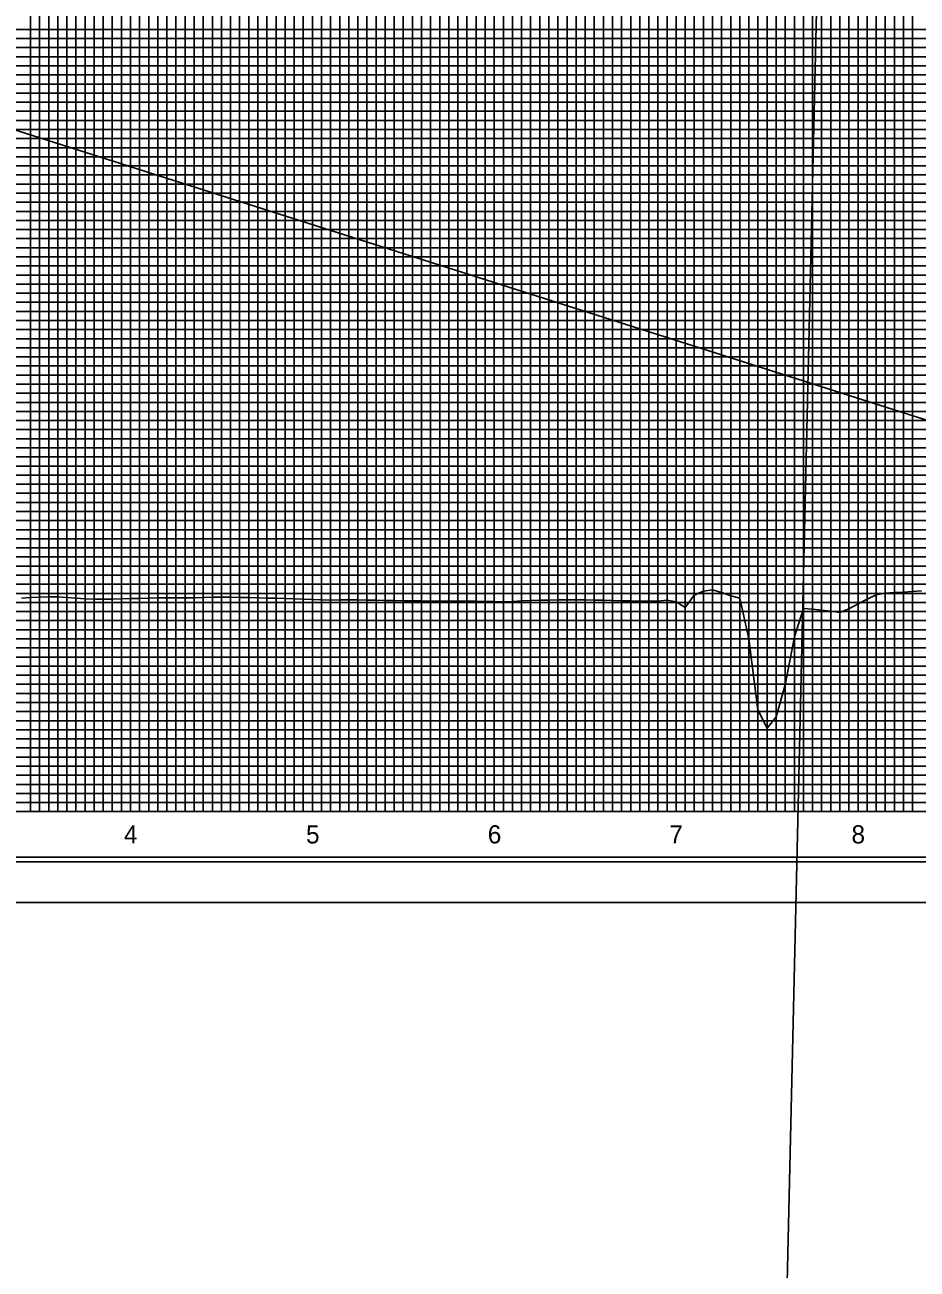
# Model space of a CAD drawing. Extents: x 2345490 to 2436403, y 465165 to 573888.
# Drawn here: x 2411237 to 2411728, y 518231 to 518915 of the extents above; entities that cross this region are included whole.
import ezdxf

# ---------------------------------------------------------------- set-up
doc = ezdxf.new("R2010")
doc.units = 0
for name, color, linetype in [('Old_Level_1', 7, 'Continuous'), ('Old_Level_18', 7, 'Continuous'), ('Old_Level_2', 7, 'Continuous'), ('Old_Level_41', 7, 'Continuous'), ('Old_Level_42', 7, 'Continuous'), ('Old_Level_43', 7, 'Continuous'), ('Old_Level_50', 7, 'Continuous'), ('Old_Level_51', 7, 'Continuous'), ('Old_Level_63', 7, 'Continuous')]:
    doc.layers.add(name, color=color, linetype=linetype)

msp = doc.modelspace()

# ---------------------------------------------------------------- linework, layer by layer
at = {"layer": 'Old_Level_1'}
for points in [[(2411395.325, 518598.98475), (2411400.325, 518598.82875), (2411405.325, 518598.682), (2411410.325, 518598.75025), (2411415.325, 518598.8525), (2411420.325, 518598.783), (2411425.325, 518598.686), (2411430.325, 518598.59425), (2411435.325, 518598.5075), (2411440.325, 518598.426), (2411445.325, 518598.34975), (2411450.325, 518598.27875), (2411455.325, 518598.21275), (2411460.325, 518598.1655), (2411465.325, 518598.126), (2411470.325, 518598.092), (2411475.325, 518598.063), (2411480.325, 518598.0395), (2411485.325, 518598.02125), (2411490.325, 518597.99725), (2411495.325, 518597.9345), (2411500.325, 518597.8095), (2411505.325, 518597.96425), (2411510.325, 518598.19725), (2411515.325, 518598.44175), (2411520.325, 518598.59925), (2411525.325, 518598.69225), (2411530.325, 518598.7865), (2411535.325, 518598.882), (2411540.325, 518598.91475), (2411545.325, 518598.7975), (2411550.325, 518598.6835), (2411555.325, 518598.5725), (2411560.325, 518598.465), (2411565.325, 518598.3605), (2411570.325, 518598.25975), (2411575.325, 518598.162), (2411580.325, 518598.1435), (2411585.325, 518598.13625), (2411590.325, 518598.67625), (2411595.325, 518597.67275), (2411600.325, 518594.612), (2411605.325, 518601.43525), (2411610.325, 518603.541), (2411615.325, 518604.4015), (2411620.325, 518602.7835), (2411625.325, 518601.10625), (2411630.325, 518599.7775), (2411635.325, 518577.3245), (2411640.325, 518538.38375), (2411645.325, 518528.2755), (2411650.325, 518534.60325), (2411655.325, 518552.0595), (2411660.325, 518578.53775), (2411665.325, 518594.14075), (2411670.325, 518593.6225), (2411675.325, 518593.13325), (2411680.325, 518592.5785), (2411685.325, 518591.92875), (2411690.325, 518593.857), (2411695.325, 518596.55175), (2411700.325, 518599.15175), (2411705.325, 518601.5265), (2411710.325, 518602.44875), (2411715.325, 518602.7755), (2411720.325, 518603.11075), (2411725.325, 518603.45425), (2411730.325, 518603.80575)], [(2411235.325, 518599.83525), (2411240.325, 518600.069), (2411245.325, 518600.30975), (2411250.325, 518600.55725), (2411255.325, 518600.51975), (2411260.325, 518600.13075), (2411265.325, 518599.74925), (2411270.325, 518599.37525), (2411275.325, 518599.10925), (2411280.325, 518599.153), (2411285.325, 518599.219), (2411290.325, 518599.344), (2411295.325, 518599.4935), (2411300.325, 518599.64125), (2411305.325, 518599.787), (2411310.325, 518599.9305), (2411315.325, 518599.93425), (2411320.325, 518599.932), (2411325.325, 518599.92825), (2411330.325, 518599.92325), (2411335.325, 518600.0605), (2411340.325, 518600.36475), (2411345.325, 518600.29), (2411350.325, 518600.21125), (2411355.325, 518600.13725), (2411360.325, 518600.06375), (2411365.325, 518599.90975), (2411370.325, 518599.766), (2411375.325, 518599.69275), (2411380.325, 518599.50575), (2411385.325, 518599.32325), (2411390.325, 518599.1495), (2411395.325, 518598.98475)]]:
    msp.add_lwpolyline(points, dxfattribs=at)
at = {"layer": 'Old_Level_18'}
msp.add_lwpolyline([(2412345.325, 519507.40475), (2410845.325, 519507.40475), (2410845.325, 518457.40475), (2412345.325, 518457.40475)], close=True, dxfattribs=at)
at = {"layer": 'Old_Level_2'}
for p, q in [((2411722.59175, 521117.51825), (2411239.1575, 499960.77)), ((2411225.325, 518859.28375), (2411745.325, 518693.59875))]:
    msp.add_line(p, q, dxfattribs=at)
at = {"layer": 'Old_Level_41'}
msp.add_line((2412345.325, 518482.40475), (2410845.325, 518482.40475), dxfattribs=at)
for points in [[(2411195.325, 518482.40475), (2411245.325, 518482.40475), (2411245.325, 519507.40475)], [(2411270.325, 519507.40475), (2411270.325, 518482.40475), (2411320.325, 518482.40475), (2411320.325, 519507.40475)], [(2411295.325, 519507.40475), (2411295.325, 518482.40475), (2411345.325, 518482.40475), (2411345.325, 519507.40475)], [(2411370.325, 519507.40475), (2411370.325, 518482.40475), (2411420.325, 518482.40475), (2411420.325, 519507.40475)], [(2411395.325, 519507.40475), (2411395.325, 518482.40475), (2411445.325, 518482.40475), (2411445.325, 519507.40475)], [(2411470.325, 519507.40475), (2411470.325, 518482.40475), (2411520.325, 518482.40475), (2411520.325, 519507.40475)], [(2411495.325, 519507.40475), (2411495.325, 518482.40475), (2411545.325, 518482.40475), (2411545.325, 519507.40475)], [(2411570.325, 519507.40475), (2411570.325, 518482.40475), (2411620.325, 518482.40475), (2411620.325, 519507.40475)], [(2411595.325, 519507.40475), (2411595.325, 518482.40475), (2411645.325, 518482.40475), (2411645.325, 519507.40475)], [(2411670.325, 519507.40475), (2411670.325, 518482.40475), (2411720.325, 518482.40475), (2411720.325, 519507.40475)], [(2411695.325, 519507.40475), (2411695.325, 518482.40475), (2411745.325, 518482.40475), (2411745.325, 519507.40475)], [(2412345.325, 518907.40475), (2410845.325, 518907.40475), (2410845.325, 518857.40475), (2412345.325, 518857.40475)], [(2412345.325, 518832.40475), (2410845.325, 518832.40475), (2410845.325, 518882.40475), (2412345.325, 518882.40475)], [(2412345.325, 518807.40475), (2410845.325, 518807.40475), (2410845.325, 518757.40475), (2412345.325, 518757.40475)], [(2412345.325, 518732.40475), (2410845.325, 518732.40475), (2410845.325, 518782.40475), (2412345.325, 518782.40475)], [(2412345.325, 518707.40475), (2410845.325, 518707.40475), (2410845.325, 518657.40475), (2412345.325, 518657.40475)], [(2412345.325, 518607.40475), (2410845.325, 518607.40475), (2410845.325, 518557.40475), (2412345.325, 518557.40475)], [(2412345.325, 518532.40475), (2410845.325, 518532.40475), (2410845.325, 518582.40475), (2412345.325, 518582.40475)], [(2412345.325, 518507.40475), (2410845.325, 518507.40475)]]:
    msp.add_lwpolyline(points, dxfattribs=at)
at = {"layer": 'Old_Level_42'}
msp.add_lwpolyline([(2412345.325, 518632.40475), (2410845.325, 518632.40475), (2410845.325, 518682.40475), (2412345.325, 518682.40475)], dxfattribs=at)
at = {"layer": 'Old_Level_43'}
for points in [[(2411225.325, 518482.40475), (2411240.325, 518482.40475), (2411240.325, 519507.40475)], [(2411250.325, 519507.40475), (2411250.325, 518482.40475), (2411255.325, 518482.40475), (2411255.325, 519507.40475)], [(2411260.325, 519507.40475), (2411260.325, 518482.40475), (2411265.325, 518482.40475), (2411265.325, 519507.40475)], [(2411275.325, 519507.40475), (2411275.325, 518482.40475), (2411280.325, 518482.40475), (2411280.325, 519507.40475)], [(2411285.325, 519507.40475), (2411285.325, 518482.40475), (2411290.325, 518482.40475), (2411290.325, 519507.40475)], [(2411300.325, 519507.40475), (2411300.325, 518482.40475), (2411305.325, 518482.40475), (2411305.325, 519507.40475)], [(2411310.325, 519507.40475), (2411310.325, 518482.40475), (2411315.325, 518482.40475), (2411315.325, 519507.40475)], [(2411325.325, 519507.40475), (2411325.325, 518482.40475), (2411330.325, 518482.40475), (2411330.325, 519507.40475)], [(2411335.325, 519507.40475), (2411335.325, 518482.40475), (2411340.325, 518482.40475), (2411340.325, 519507.40475)], [(2411350.325, 519507.40475), (2411350.325, 518482.40475), (2411355.325, 518482.40475), (2411355.325, 519507.40475)], [(2411360.325, 519507.40475), (2411360.325, 518482.40475), (2411365.325, 518482.40475), (2411365.325, 519507.40475)], [(2411375.325, 519507.40475), (2411375.325, 518482.40475)], [(2411380.325, 519507.40475), (2411380.325, 518482.40475), (2411385.325, 518482.40475), (2411385.325, 519507.40475), (2411390.325, 519507.40475), (2411390.325, 518482.40475), (2411400.325, 518482.40475), (2411400.325, 519507.40475), (2411405.325, 519507.40475), (2411405.325, 518482.40475), (2411410.325, 518482.40475), (2411410.325, 519507.40475), (2411415.325, 519507.40475), (2411415.325, 518482.40475)], [(2411425.325, 518482.40475), (2411425.325, 519507.40475)], [(2411430.325, 519507.40475), (2411430.325, 518482.40475), (2411435.325, 518482.40475), (2411435.325, 519507.40475)], [(2411440.325, 519507.40475), (2411440.325, 518482.40475), (2411450.325, 518482.40475), (2411450.325, 519507.40475)], [(2411455.325, 519507.40475), (2411455.325, 518482.40475), (2411455.325, 518482.40475), (2411460.325, 518482.40475), (2411460.325, 519507.40475)], [(2411465.325, 519507.40475), (2411465.325, 518482.40475), (2411475.325, 518482.40475), (2411475.325, 519507.40475)], [(2411480.325, 519507.40475), (2411480.325, 518482.40475), (2411485.325, 518482.40475), (2411485.325, 519507.40475)], [(2411490.325, 519507.40475), (2411490.325, 518482.40475), (2411500.325, 518482.40475), (2411500.325, 519507.40475)], [(2411505.325, 519507.40475), (2411505.325, 518482.40475), (2411510.325, 518482.40475), (2411510.325, 519507.40475)], [(2411515.325, 519507.40475), (2411515.325, 518482.40475), (2411525.325, 518482.40475), (2411525.325, 519507.40475)], [(2411530.325, 519507.40475), (2411530.325, 518482.40475), (2411535.325, 518482.40475), (2411535.325, 519507.40475)], [(2411540.325, 519507.40475), (2411540.325, 518482.40475), (2411550.325, 518482.40475), (2411550.325, 519507.40475)], [(2411555.325, 519507.40475), (2411555.325, 518482.40475), (2411560.325, 518482.40475), (2411560.325, 519507.40475)], [(2411565.325, 519507.40475), (2411565.325, 518482.40475), (2411575.325, 518482.40475), (2411575.325, 519507.40475)], [(2411580.325, 519507.40475), (2411580.325, 518482.40475), (2411585.325, 518482.40475), (2411585.325, 519507.40475)], [(2411590.325, 519507.40475), (2411590.325, 518482.40475), (2411600.325, 518482.40475), (2411600.325, 519507.40475)], [(2411605.325, 519507.40475), (2411605.325, 518482.40475)], [(2411605.325, 518482.40475), (2411610.325, 518482.40475), (2411610.325, 519506.80475)], [(2411615.325, 519506.80475), (2411615.325, 518482.40475), (2411625.325, 518482.40475), (2411625.325, 519507.40475)], [(2411630.325, 519507.40475), (2411630.325, 518482.40475), (2411635.325, 518482.40475), (2411635.325, 519507.40475)], [(2411640.325, 519507.40475), (2411640.325, 518482.40475), (2411650.325, 518482.40475), (2411650.325, 519507.40475)], [(2411655.325, 519507.40475), (2411655.325, 518482.40475), (2411660.325, 518482.40475), (2411660.325, 519507.40475)], [(2411665.325, 519507.40475), (2411665.325, 518482.40475), (2411675.325, 518482.40475), (2411675.325, 519507.40475)], [(2411680.325, 519507.40475), (2411680.325, 518482.40475), (2411685.325, 518482.40475), (2411685.325, 519507.40475)], [(2411690.325, 519507.40475), (2411690.325, 518482.40475), (2411700.325, 518482.40475), (2411700.325, 519507.40475)], [(2411705.325, 519507.40475), (2411705.325, 518482.40475), (2411710.325, 518482.40475), (2411710.325, 519507.40475)], [(2411715.325, 519507.40475), (2411715.325, 518482.40475), (2411725.325, 518482.40475), (2411725.325, 519507.40475)], [(2412295.325, 518912.40475), (2410895.325, 518912.40475), (2410895.325, 518902.40475), (2412295.325, 518902.40475)], [(2412295.325, 518897.40475), (2410895.325, 518897.40475), (2410895.325, 518892.40475), (2412295.325, 518892.40475)], [(2412295.325, 518887.40475), (2410895.325, 518887.40475), (2410895.325, 518877.40475), (2412295.325, 518877.40475)], [(2412295.325, 518872.40475), (2410895.325, 518872.40475), (2410895.325, 518867.40475), (2412295.325, 518867.40475)], [(2412295.325, 518862.40475), (2410895.325, 518862.40475), (2410895.325, 518852.40475), (2412295.325, 518852.40475)], [(2412295.325, 518847.40475), (2410895.325, 518847.40475), (2410895.325, 518842.40475), (2412295.325, 518842.40475)], [(2412295.325, 518837.40475), (2410895.325, 518837.40475), (2410895.325, 518827.40475), (2412295.325, 518827.40475)], [(2412295.325, 518822.40475), (2410895.325, 518822.40475), (2410895.325, 518817.40475), (2412295.325, 518817.40475)], [(2412295.325, 518812.40475), (2410895.325, 518812.40475), (2410895.325, 518802.40475), (2412295.325, 518802.40475)], [(2412295.325, 518797.40475), (2410895.325, 518797.40475), (2410895.325, 518792.40475), (2412295.325, 518792.40475)], [(2412295.325, 518787.40475), (2410895.325, 518787.40475), (2410895.325, 518777.40475), (2412295.325, 518777.40475)], [(2412295.325, 518772.40475), (2410895.325, 518772.40475), (2410895.325, 518767.40475), (2412295.325, 518767.40475)], [(2412295.325, 518762.40475), (2410895.325, 518762.40475), (2410895.325, 518752.40475), (2412295.325, 518752.40475)], [(2412295.325, 518747.40475), (2410895.325, 518747.40475), (2410895.325, 518742.40475), (2412295.325, 518742.40475)], [(2412295.325, 518737.40475), (2410895.325, 518737.40475), (2410895.325, 518727.40475), (2412295.325, 518727.40475)], [(2412295.325, 518722.40475), (2410895.325, 518722.40475), (2410895.325, 518717.40475), (2412295.325, 518717.40475)], [(2412295.325, 518712.40475), (2410895.325, 518712.40475), (2410895.325, 518702.40475), (2412295.325, 518702.40475)], [(2412295.325, 518697.40475), (2410895.325, 518697.40475), (2410895.325, 518692.40475), (2412295.325, 518692.40475)], [(2412295.325, 518687.40475), (2410895.325, 518687.40475)], [(2410895.325, 518677.40475), (2412295.325, 518677.40475)], [(2412295.325, 518672.40475), (2410895.325, 518672.40475), (2410895.325, 518667.40475), (2412295.325, 518667.40475)], [(2412295.325, 518662.40475), (2410895.325, 518662.40475)], [(2410895.325, 518652.40475), (2412295.325, 518652.40475)], [(2412295.325, 518647.40475), (2410895.325, 518647.40475), (2410895.325, 518642.40475), (2412295.325, 518642.40475)], [(2412295.325, 518637.40475), (2410895.325, 518637.40475), (2410895.325, 518627.40475), (2412295.325, 518627.40475)], [(2412295.325, 518622.40475), (2410895.325, 518622.40475), (2410895.325, 518617.40475), (2412295.325, 518617.40475)], [(2412295.325, 518612.40475), (2410895.325, 518612.40475), (2410895.325, 518602.40475), (2412295.325, 518602.40475)], [(2412295.325, 518597.40475), (2410895.325, 518597.40475), (2410895.325, 518592.40475), (2412295.325, 518592.40475)], [(2412295.325, 518587.40475), (2410895.325, 518587.40475), (2410895.325, 518577.40475), (2412295.325, 518577.40475)], [(2412295.325, 518572.40475), (2410895.325, 518572.40475), (2410895.325, 518567.40475), (2412295.325, 518567.40475)], [(2412295.325, 518562.40475), (2410895.325, 518562.40475), (2410895.325, 518552.40475), (2412295.325, 518552.40475)], [(2412295.325, 518547.40475), (2410895.325, 518547.40475), (2410895.325, 518542.40475), (2412295.325, 518542.40475)], [(2412295.325, 518537.40475), (2410895.325, 518537.40475), (2410895.325, 518527.40475), (2412295.325, 518527.40475)], [(2412295.325, 518522.40475), (2410895.325, 518522.40475), (2410895.325, 518517.40475), (2412295.325, 518517.40475)], [(2412295.325, 518512.40475), (2410895.325, 518512.40475), (2410895.325, 518502.40475), (2412295.325, 518502.40475)], [(2412295.325, 518497.40475), (2410895.325, 518497.40475), (2410895.325, 518492.40475), (2412295.325, 518492.40475)], [(2412295.325, 518487.40475), (2410895.325, 518487.40475)]]:
    msp.add_lwpolyline(points, dxfattribs=at)
at = {"layer": 'Old_Level_50'}
msp.add_lwpolyline([(2412357.825, 519509.95475), (2410691.325, 519509.95475), (2410691.325, 518454.85475), (2412357.825, 518454.85475)], close=True, dxfattribs=at)
at = {"layer": 'Old_Level_51'}
msp.add_lwpolyline([(2412362.325, 519532.40475), (2410678.325, 519532.40475), (2410678.325, 518432.40475), (2412362.325, 518432.40475)], close=True, dxfattribs=at)
at = {"layer": 'Old_Level_63'}
msp.add_line((2410895.325, 518482.40475), (2412469.0995, 518482.40475), dxfattribs=at)

# ---------------------------------------------------------------- texts
at = {"layer": 'Old_Level_1'}
for s, p in [('4', (2411291.731, 518464.90475)), ('5', (2411391.8235, 518464.90475)), ('6', (2411491.7645, 518464.90475)), ('7', (2411591.622, 518464.90475)), ('8', (2411691.748, 518464.90475))]:
    msp.add_text(s, height=10, dxfattribs=at).set_placement(p)

doc.saveas('drawing.dxf')
